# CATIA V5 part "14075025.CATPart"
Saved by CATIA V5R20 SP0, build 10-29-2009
Part number: 14075025
Definition: NONE
Nomenclature: 14075025
Source: Unknown
Description: 14075025
Bounding box of the stored display mesh (mm): x -12.5 to 50, y -51.5 to 41.58, z -41.6 to 41.6
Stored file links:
  C:\Users\Utente\Desktop\IO LAVORO\3D X SITO CF\X SITO\PLASTICA\RF2\14075025.CATPart
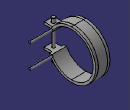
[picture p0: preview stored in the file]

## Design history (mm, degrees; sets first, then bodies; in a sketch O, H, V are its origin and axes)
Body1 "14075025" (main body)
  Solid1: solid without history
